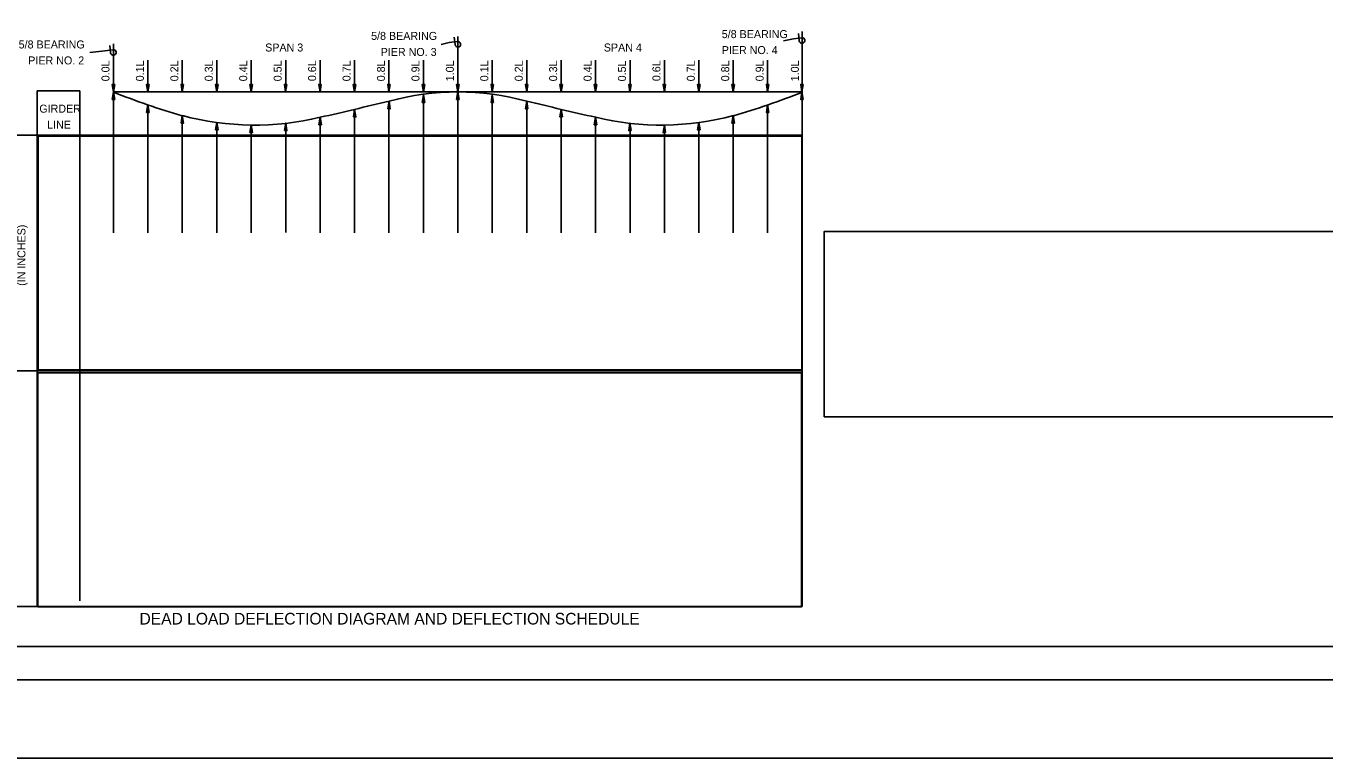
# Model space of a CAD drawing. Extents: x 4944 to 17449, y 3824 to 49087.
# Drawn here: x 11084 to 12953, y 5763 to 6818 of the extents above; entities that cross this region are included whole.
import ezdxf

# ---------------------------------------------------------------- set-up
doc = ezdxf.new("R2010")
doc.units = 0
for name, color, linetype in [('1', 7, 'Continuous'), ('36_S_LINES', 7, 'Continuous'), ('37_S_TXT', 7, 'Continuous'), ('3A', 7, 'Continuous'), ('4', 7, 'Continuous'), ('6', 7, 'Continuous'), ('7', 7, 'Continuous'), ('BEAM', 7, 'Continuous'), ('DIM', 7, 'Continuous'), ('Level 14', 7, 'Continuous'), ('Level 34', 7, 'Continuous')]:
    doc.layers.add(name, color=color, linetype=linetype)

# ---------------------------------------------------------------- blocks, each defined once
blk = doc.blocks.new('DWG010')
at = {"layer": '1'}
for p, q in [((0, 0.047), (0.141, 0.047)), ((0.047, 0), (0.047, 0.125))]:
    blk.add_line(p, q, dxfattribs=at)
blk.add_arc((0, 0), 0.0469, 90, 0, dxfattribs=at)
blk = doc.blocks.new('ARROWH')
at = {"layer": '1'}
blk.add_lwpolyline([(0.123, -0.021), (0.123, 0.021), (-0.002, 0)], close=True, dxfattribs=at)

msp = doc.modelspace()

# ---------------------------------------------------------------- linework, layer by layer
at = {"layer": '36_S_LINES'}
for points in [[(11101.7, 6322.5), (12201.3, 6322.5), (12201.3, 6659.4), (11101.7, 6659.4)], [(11101.2, 5981.3), (12200.8, 5981.3), (12200.8, 6318.2), (11101.2, 6318.2)]]:
    msp.add_lwpolyline(points, close=True, dxfattribs=at)
at = {"layer": '37_S_TXT'}
msp.add_lwpolyline([(10621.1, 8067.3), (14077.1, 8067.3), (14077.1, 5763.3), (10621.1, 5763.3)], close=True, dxfattribs=at)
at = {"layer": '3A'}
for p, q in [((11706.1, 6803), (11706.1, 6722.9)), ((12201.6, 6810), (12201.6, 6660.9)), ((11210.2, 6792.1), (11210.2, 6722.9))]:
    msp.add_line(p, q, dxfattribs=at)
at = {"layer": '4'}
msp.add_line((11211.3, 6660.9), (11960.6, 6660.9), dxfattribs=at)
at = {"layer": '6'}
for p, q in [((11693.6, 6794.1), (11682.2, 6791.4)), ((12189.1, 6799.5), (12174.7, 6796.8)), ((11197.7, 6782.3), (11176.2, 6779.6)), ((11259.8, 6722.9), (11259.8, 6768.7)), ((11309.4, 6722.9), (11309.4, 6768.7)), ((11359, 6722.9), (11359, 6768.7)), ((11408.6, 6722.9), (11408.6, 6768.7)), ((11458.2, 6722.9), (11458.2, 6768.7)), ((11507.8, 6723.1), (11507.8, 6768.9)), ((11557.3, 6722.9), (11557.3, 6768.7)), ((11606.9, 6722.9), (11606.9, 6768.7)), ((11656.5, 6722.9), (11656.5, 6768.7)), ((11755.7, 6722.9), (11755.7, 6768.7)), ((11805.2, 6722.9), (11805.2, 6768.7)), ((11854.8, 6722.9), (11854.8, 6768.7)), ((11904.3, 6722.9), (11904.3, 6768.7)), ((11953.9, 6722.7), (11953.9, 6768.5)), ((12003.4, 6723.1), (12003.4, 6768.9)), ((12052.9, 6722.9), (12052.9, 6768.7)), ((12102.5, 6722.9), (12102.5, 6768.7)), ((12152, 6722.9), (12152, 6768.7)), ((11210.2, 6520.1), (11210.2, 6722.9)), ((11210.2, 6722.9), (11210.2, 6722.9)), ((11259.8, 6722.9), (11259.8, 6722.9)), ((11309.4, 6722.9), (11309.4, 6722.9)), ((11359, 6722.9), (11359, 6722.9)), ((11408.6, 6722.9), (11408.6, 6722.9)), ((11458.2, 6722.9), (11458.2, 6722.9)), ((11507.8, 6722.9), (11507.8, 6722.9)), ((11557.3, 6722.9), (11557.3, 6722.9)), ((11606.9, 6722.9), (11606.9, 6722.9)), ((11606.9, 6520.1), (11606.9, 6709.6)), ((11656.5, 6722.9), (11656.5, 6722.9)), ((11656.5, 6520.1), (11656.5, 6718.9)), ((11706.1, 6520.1), (11706.1, 6722.9)), ((11706.1, 6722.9), (11706.1, 6722.9)), ((11755.7, 6722.9), (11755.7, 6722.9)), ((11755.7, 6520.1), (11755.7, 6718.9)), ((11805.2, 6722.9), (11805.2, 6722.9)), ((11805.2, 6520.1), (11805.2, 6709.6)), ((11854.8, 6722.9), (11854.8, 6722.9)), ((11904.3, 6722.9), (11904.3, 6722.9)), ((11953.8, 6722.9), (11953.8, 6722.9)), ((12003.4, 6722.9), (12003.4, 6722.9)), ((12052.9, 6722.9), (12052.9, 6722.9)), ((12102.5, 6722.9), (12102.5, 6722.9)), ((12152, 6722.9), (12152, 6722.9)), ((12201.6, 6722.9), (12201.6, 6722.9)), ((11259.8, 6520.1), (11259.8, 6704.3)), ((11557.3, 6520.1), (11557.3, 6697.8)), ((11854.8, 6520.1), (11854.8, 6697.8)), ((12152, 6520.1), (12152, 6704.3)), ((11309.4, 6520.1), (11309.4, 6688.8)), ((11359, 6520.1), (11359, 6678.9)), ((11408.6, 6520.1), (11408.6, 6675.2)), ((11458.2, 6520.3), (11458.2, 6678.1)), ((11507.8, 6520.1), (11507.8, 6686.3)), ((11904.3, 6520.1), (11904.3, 6686.3)), ((11953.9, 6520.1), (11953.9, 6677.9)), ((12003.4, 6520.1), (12003.4, 6675.2)), ((12052.9, 6520.1), (12052.9, 6678.9)), ((12102.5, 6520.1), (12102.5, 6688.8))]:
    msp.add_line(p, q, dxfattribs=at)
at = {"layer": '7'}
for p, q in [((11210.2, 6722.9), (11706.1, 6722.9)), ((11706.1, 6722.9), (12201.6, 6722.9))]:
    msp.add_line(p, q, dxfattribs=at)
at = {"layer": 'BEAM'}
for centre, radius, start, end in [((11564.5, 7592.1), 938.7, 247.8233, 254.2284), ((9595.6, 15066.5), 8595.5, 282.85378, 283.53281), ((11706.1, 6347.6), 375.3, 74.6834, 105.3166), ((13816.7, 15066.5), 8595.5, 256.46719, 257.14622), ((11847.7, 7592.1), 938.7, 285.7716, 292.1767), ((11413.5, 7078.1), 402.9, 255.0329, 283.5345), ((11998.8, 7078.1), 402.9, 256.4655, 284.9671)]:
    msp.add_arc(centre, radius, start, end, dxfattribs=at)
at = {"layer": 'DEFPOINTS'}
msp.add_lwpolyline([(12233.5, 6255), (13941.2, 6255), (13941.2, 6521.9), (12233.5, 6521.9)], close=True, dxfattribs=at)
at = {"layer": 'DIM'}
msp.add_lwpolyline([(10778.3, 7988.1), (14042.3, 7988.1), (14042.3, 5876.1), (10778.3, 5876.1)], close=True, dxfattribs=at)
at = {"layer": 'Level 14'}
msp.add_lwpolyline([(13989.5, 5924.1), (10965.5, 5924.1), (10965.5, 7940.1), (13989.5, 7940.1)], close=True, dxfattribs=at)
at = {"layer": 'Level 34'}
for p, q in [((11100.6, 5981.6), (11100.6, 6724.5)), ((11161.8, 6724.5), (11100.6, 6724.5)), ((11161.8, 5989.9), (11161.8, 6724.5)), ((12201.6, 6660.9), (10999.3, 6660.9)), ((12201.6, 5981.6), (12201.6, 6660.9)), ((10999.3, 6321), (12201.6, 6321)), ((10999.3, 5981.6), (12201.6, 5981.6))]:
    msp.add_line(p, q, dxfattribs=at)

# ---------------------------------------------------------------- block references
at = {"layer": '6'}
for name, p, xscale, yscale, rotation in [('DWG010', (11706.1, 6791.6), 85.92279574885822, -85.92279574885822, -172.86861111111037), ('DWG010', (12201.6, 6797), 85.92279574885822, -85.92279574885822, -172.8686111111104), ('DWG010', (11210.2, 6779.8), 85.92279574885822, -85.9227957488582, -172.86861111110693), ('ARROWH', (11210.2, 6723.1), 85.9227957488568, 85.9227957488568, 90), ('ARROWH', (11259.8, 6723.1), 85.9227957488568, 85.9227957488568, 90), ('ARROWH', (11309.4, 6723.1), 85.9227957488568, 85.9227957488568, 90), ('ARROWH', (11359, 6723.1), 85.9227957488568, 85.9227957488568, 90), ('ARROWH', (11408.6, 6723.1), 85.9227957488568, 85.9227957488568, 90), ('ARROWH', (11458.1, 6723.1), 85.9227957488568, 85.9227957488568, 90), ('ARROWH', (11507.7, 6723.2), 85.9227957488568, 85.9227957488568, 90), ('ARROWH', (11557.3, 6723.1), 85.9227957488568, 85.9227957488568, 90), ('ARROWH', (11606.9, 6723.1), 85.9227957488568, 85.9227957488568, 90), ('ARROWH', (11656.5, 6723.1), 85.9227957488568, 85.9227957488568, 90), ('ARROWH', (11706.1, 6723.1), 85.9227957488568, 85.9227957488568, 90), ('ARROWH', (11755.6, 6723.1), 85.9227957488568, 85.9227957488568, 90), ('ARROWH', (11805.2, 6723.1), 85.9227957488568, 85.9227957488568, 90), ('ARROWH', (11854.7, 6723.1), 85.9227957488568, 85.9227957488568, 90), ('ARROWH', (11904.3, 6723.1), 85.9227957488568, 85.9227957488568, 90), ('ARROWH', (11953.8, 6722.9), 85.9227957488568, 85.9227957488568, 90), ('ARROWH', (12003.4, 6723.2), 85.9227957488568, 85.9227957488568, 90), ('ARROWH', (12052.9, 6723.1), 85.9227957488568, 85.9227957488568, 90), ('ARROWH', (12102.4, 6723.1), 85.9227957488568, 85.9227957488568, 90), ('ARROWH', (12152, 6723.1), 85.9227957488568, 85.9227957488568, 90), ('ARROWH', (12201.5, 6723.1), 85.9227957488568, 85.9227957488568, 90), ('ARROWH', (11210.3, 6722.7), 85.92279574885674, 85.92279574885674, -90.00000000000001), ('ARROWH', (11607, 6709.4), 85.92279574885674, 85.92279574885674, -90.00000000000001), ('ARROWH', (11656.6, 6718.5), 85.92279574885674, 85.92279574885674, -90.00000000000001), ('ARROWH', (11706.1, 6722.7), 85.92279574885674, 85.92279574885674, -90.00000000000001), ('ARROWH', (11755.6, 6718.5), 85.92279574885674, -85.92279574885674, -90.00000000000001), ('ARROWH', (11805.2, 6709.4), 85.92279574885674, -85.92279574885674, -90.00000000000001), ('ARROWH', (12201.5, 6722.7), 85.92279574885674, -85.9227957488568, -90.00000000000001), ('ARROWH', (11259.8, 6704.1), 85.92279574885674, 85.92279574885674, -90.00000000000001), ('ARROWH', (11557.4, 6697.6), 85.92279574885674, 85.92279574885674, -90.00000000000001), ('ARROWH', (11854.7, 6697.6), 85.92279574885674, -85.92279574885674, -90.00000000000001), ('ARROWH', (12152, 6704.1), 85.92279574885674, -85.92279574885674, -90.00000000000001), ('ARROWH', (11309.4, 6688.6), 85.92279574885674, 85.92279574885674, -90.00000000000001), ('ARROWH', (11359, 6678.7), 85.92279574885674, 85.92279574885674, -90.00000000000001), ('ARROWH', (11408.6, 6675), 85.92279574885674, 85.92279574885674, -90.00000000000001), ('ARROWH', (11458.2, 6677.9), 85.92279574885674, 85.92279574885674, -90.00000000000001), ('ARROWH', (11507.8, 6686.2), 85.92279574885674, 85.92279574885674, -90.00000000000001), ('ARROWH', (11904.3, 6686.2), 85.92279574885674, -85.92279574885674, -90.00000000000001), ('ARROWH', (11953.8, 6677.8), 85.92279574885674, -85.92279574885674, -90.00000000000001), ('ARROWH', (12003.4, 6675), 85.92279574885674, -85.92279574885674, -90.00000000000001), ('ARROWH', (12052.9, 6678.7), 85.92279574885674, -85.92279574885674, -90.00000000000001), ('ARROWH', (12102.4, 6688.6), 85.92279574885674, -85.92279574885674, -90.00000000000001)]:
    msp.add_blockref(name, p, dxfattribs=dict(at, xscale=xscale, yscale=yscale, rotation=rotation))

# ---------------------------------------------------------------- texts
at = {"layer": '3A'}
for s, p in [('5/8 BEARING ', (11581.2, 6797.9)), ('5/8 BEARING ', (12086, 6800.5)), ('5/8 BEARING ', (11073.8, 6785.6)), ('SPAN 3', (11428.7, 6781.2)), ('PIER NO. 3', (11595, 6774.8)), ('SPAN 4', (11916.2, 6781.2)), ('PIER NO. 4', (12086, 6777.5)), ('PIER NO. 2', (11087.6, 6762.6)), ('GIRDER', (11103.5, 6693.1)), ('LINE', (11114.8, 6670.1))]:
    msp.add_text(s, height=11.52, dxfattribs=at).set_placement(p)
for s, p in [('0.0L', (11204.5, 6738.3)), ('0.1L', (11254.1, 6738.3)), ('0.2L', (11303.7, 6738.3)), ('0.3L', (11353.2, 6738.3)), ('0.4L', (11402.8, 6738.3)), ('0.5L', (11452.4, 6738.3)), ('0.6L', (11502, 6738.5)), ('0.7L', (11551.6, 6738.3)), ('0.8L', (11601.2, 6738.3)), ('0.9L', (11650.8, 6738.3)), ('1.0L', (11700.3, 6738.3)), ('0.1L', (11749.9, 6738.3)), ('0.2L', (11799.5, 6738.3)), ('0.3L', (11849, 6738.3)), ('0.4L', (11898.6, 6738.3)), ('0.5L', (11948.1, 6738.2)), ('0.6L', (11997.7, 6738.5)), ('0.7L', (12047.2, 6738.3)), ('0.8L', (12096.7, 6738.3)), ('0.9L', (12146.3, 6738.3)), ('1.0L', (12197, 6738.3)), ('(IN INCHES)', (11083.5, 6443.6))]:
    msp.add_text(s, height=11.52, rotation=90, dxfattribs=at).set_placement(p)
at = {"layer": 'BEAM'}
msp.add_text('DEAD LOAD DEFLECTION DIAGRAM AND DEFLECTION SCHEDULE', height=16.8, dxfattribs=at).set_placement((11247.7, 5955.7))

doc.saveas('drawing.dxf')
